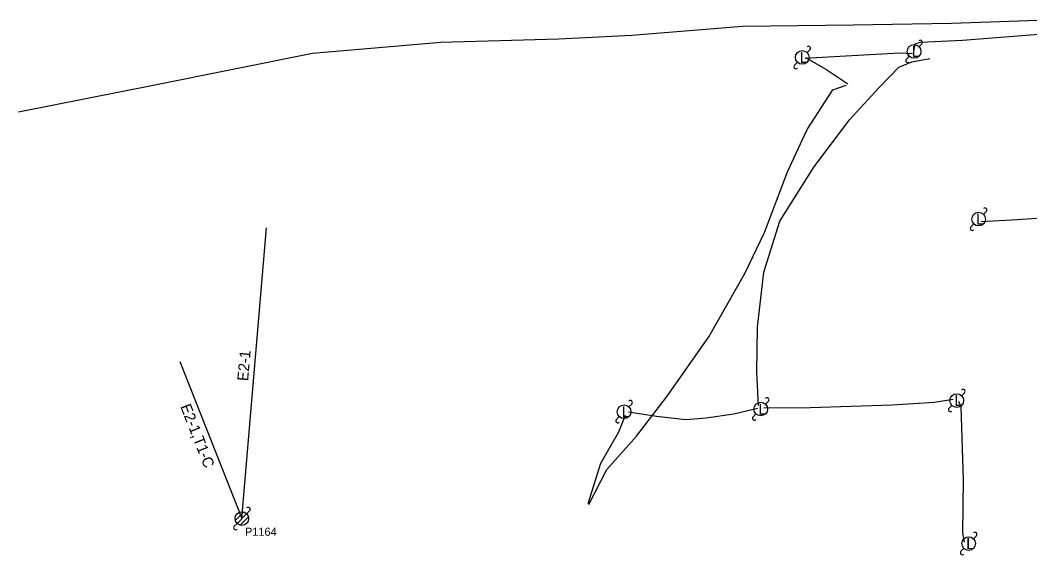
# Model space of a CAD drawing. Extents: x 1614474 to 1865144, y 1098877 to 1212550.
# Drawn here: x 1810361.4 to 1810731.8, y 1189813.3 to 1190009.3 of the extents above; entities that cross this region are included whole.
import ezdxf

# ---------------------------------------------------------------- set-up
doc = ezdxf.new("R2010")
doc.units = 0
for name, color, linetype in [('RD_EX_SU_Elec', 7, 'Continuous'), ('RD_EX_SU_Gas', 7, 'Continuous'), ('RD_EX_SU_Ovhd', 7, 'Continuous'), ('RD_EX_SU_Pole', 7, 'Continuous'), ('RD_EX_SU_TX_Pole', 7, 'Continuous')]:
    doc.layers.add(name, color=color, linetype=linetype)

# ---------------------------------------------------------------- blocks, each defined once
blk = doc.blocks.new('SUE_PP')
at = {"layer": 'RD_EX_SU_Pole'}
for p, q in [((-2.41, -0.65), (0.65, 2.41)), ((-1.77, -1.77), (1.77, 1.77)), ((-0.65, -2.41), (2.41, 0.65)), ((1.77, 1.77), (2.83, 2.83)), ((-2.83, -2.83), (-1.77, -1.77))]:
    blk.add_line(p, q, dxfattribs=at)
blk.add_circle((0, 0), 2.5, dxfattribs=at)
for centre, start, end in [((2.3, 3.36), 315, 135), ((-2.3, -3.36), 135, 315)]:
    blk.add_arc(centre, 0.75, start, end, dxfattribs=at)

msp = doc.modelspace()

# ---------------------------------------------------------------- linework, layer by layer
at = {"layer": 'RD_EX_SU_Elec'}
for points in [[(1810689.38, 1189998.41), (1810689.68, 1190000.63), (1810691.68, 1190001.24), (1810707.07, 1190001.91), (1810735.1, 1190004.09), (1810751.67, 1190003.88), (1810753.03, 1190002.58), (1810753.21, 1190001.46)], [(1810632.17, 1189868.03), (1810631.62, 1189880.27), (1810631.82, 1189896.78), (1810634.23, 1189916.89), (1810640.01, 1189935.59), (1810652.51, 1189955.38), (1810665.66, 1189972.7), (1810676.35, 1189984.52), (1810683.7, 1189992.06), (1810688.45, 1189993.95), (1810695.02, 1189995.25)], [(1810649.4, 1189995.34), (1810662.04, 1189996.13), (1810684.1, 1189997.27), (1810688.66, 1189997.01)], [(1810649.5, 1189995.56), (1810656.92, 1189991.27), (1810664.99, 1189985.89)], [(1810569.96, 1189831.7), (1810576.53, 1189844.54), (1810587.41, 1189856.76), (1810598.7, 1189871.38), (1810614.01, 1189893.17), (1810627.25, 1189916.45), (1810634.46, 1189931.47), (1810642.82, 1189953.65), (1810650.1, 1189969.23), (1810659.48, 1189983.75), (1810664.39, 1189985.49)], [(1810713.88, 1189935.52), (1810727.23, 1189936.17), (1810744.67, 1189937.45), (1810767.73, 1189940.04), (1810776.98, 1189940.35)], [(1810634.12, 1189867.14), (1810651.15, 1189867.24), (1810681.2, 1189868.26), (1810696.71, 1189869.18), (1810703.59, 1189870.37)], [(1810707.76, 1189817.87), (1810707.2, 1189821.31), (1810707.42, 1189840.71), (1810706.54, 1189867.52), (1810705.68, 1189869.44)], [(1810584.48, 1189865.7), (1810594.86, 1189864.03), (1810605.53, 1189862.81), (1810613.03, 1189863.44), (1810623.12, 1189864.97), (1810631.84, 1189867.06)], [(1810569.7, 1189832.07), (1810574.42, 1189846.88), (1810581.01, 1189858.31), (1810583.43, 1189864.5)]]:
    msp.add_lwpolyline(points, dxfattribs=at)
at = {"layer": 'RD_EX_SU_Gas'}
msp.add_lwpolyline([(1810360.73, 1189975.64), (1810410.81, 1189985.57), (1810468.67, 1189997.18), (1810515.69, 1190001.21), (1810558.98, 1190002.44), (1810585.76, 1190003.83), (1810626.31, 1190007.08), (1810666.92, 1190007.6), (1810703.04, 1190008.2), (1810734.82, 1190009.27)], dxfattribs=at)
at = {"layer": 'RD_EX_SU_Ovhd'}
for p, q in [((1810442.69, 1189826.54), (1810451.79, 1189933.09)), ((1810419.99, 1189884.17), (1810442.69, 1189826.54))]:
    msp.add_line(p, q, dxfattribs=at)
at = {"layer": 'RD_EX_SU_Pole'}
for p, q in [((1810650.02, 1189997.37), (1810651.08, 1189998.43)), ((1810691.09, 1189999.56), (1810692.15, 1190000.62)), ((1810686.49, 1189994.97), (1810687.55, 1189996.03)), ((1810645.42, 1189992.77), (1810646.48, 1189993.83)), ((1810714.74, 1189938.09), (1810715.8, 1189939.15)), ((1810710.15, 1189933.5), (1810711.21, 1189934.56)), ((1810706.71, 1189871.58), (1810707.77, 1189872.64)), ((1810584.7, 1189867.49), (1810585.76, 1189868.55)), ((1810634.81, 1189868.47), (1810635.88, 1189869.53)), ((1810630.22, 1189863.87), (1810631.28, 1189864.93)), ((1810702.12, 1189866.98), (1810703.18, 1189868.04)), ((1810580.1, 1189862.89), (1810581.16, 1189863.95)), ((1810711.08, 1189819.14), (1810712.15, 1189820.2)), ((1810706.49, 1189814.54), (1810707.55, 1189815.6))]:
    msp.add_line(p, q, dxfattribs=at)
for centre in [(1810689.32, 1189997.8), (1810648.25, 1189995.6), (1810712.98, 1189936.33), (1810704.95, 1189869.81), (1810633.05, 1189866.7), (1810582.93, 1189865.72), (1810709.32, 1189817.37)]:
    msp.add_circle(centre, 2.5, dxfattribs=at)
for centre, start, end in [((1810691.62, 1190001.15), 315, 135), ((1810650.55, 1189998.96), 315, 135), ((1810687.02, 1189994.44), 135, 315), ((1810645.95, 1189992.24), 135, 315), ((1810715.27, 1189939.68), 315, 135), ((1810710.68, 1189932.97), 135, 315), ((1810707.24, 1189873.17), 315, 135), ((1810585.23, 1189869.08), 315, 135), ((1810635.35, 1189870.06), 315, 135), ((1810702.65, 1189866.45), 135, 315), ((1810580.63, 1189862.36), 135, 315), ((1810630.75, 1189863.34), 135, 315), ((1810711.62, 1189820.73), 315, 135), ((1810707.02, 1189814.01), 135, 315)]:
    msp.add_arc(centre, 0.75, start, end, dxfattribs=at)

# ---------------------------------------------------------------- block references
msp.add_blockref('SUE_PP', (1810442.69, 1189826.54), dxfattribs=at)

# ---------------------------------------------------------------- texts
at = {"layer": 'RD_EX_SU_Ovhd'}
for s, rotation, p in [('E2-1', 85.1171, (1810444.98, 1189876.84)), ('E2-1,T1-C', 291.494, (1810420.05, 1189867.65))]:
    msp.add_text(s, height=4, rotation=rotation, dxfattribs=at).set_placement(p)
at = {"layer": 'RD_EX_SU_Pole'}
for p in [(1810688.46, 1189995.8), (1810647.39, 1189993.6), (1810712.11, 1189934.33), (1810632.18, 1189864.7), (1810704.08, 1189867.81), (1810582.07, 1189863.72), (1810708.45, 1189815.37)]:
    msp.add_text('L', height=4, dxfattribs=at).set_placement(p)
at = {"layer": 'RD_EX_SU_TX_Pole'}
msp.add_text('P1164', height=3, dxfattribs=at).set_placement((1810443.86, 1189820.22))

doc.saveas('drawing.dxf')
